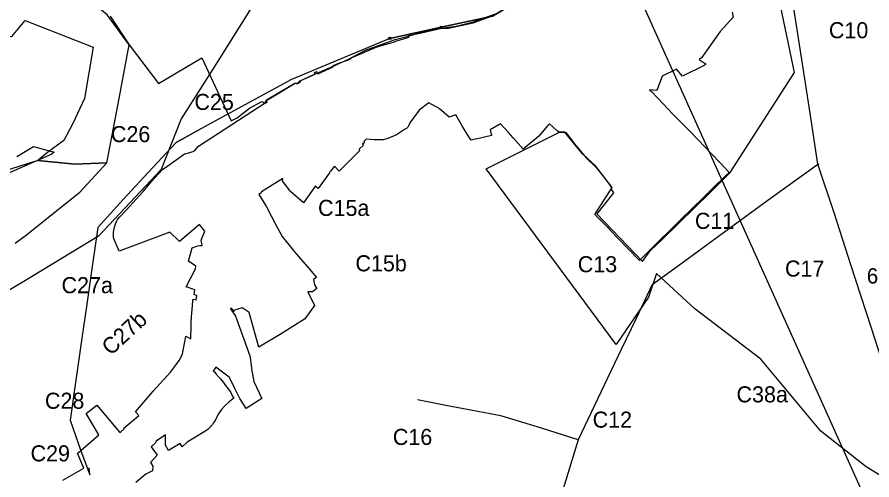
# Model space of a CAD drawing. Extents: x -557103 to -548162, y -1041918 to -1033974.
# Drawn here: x -553807 to -552210, y -1037353 to -1036489 of the extents above; entities that cross this region are included whole.
import ezdxf

# ---------------------------------------------------------------- set-up
doc = ezdxf.new("R2010")
doc.units = 0
for name, color, linetype in [('body3', 7, 'Continuous'), ('Vrstva 14', 7, 'Continuous'), ('Vrstva 15', 7, 'Continuous'), ('Vrstva 16', 7, 'Continuous'), ('Vrstva 37', 7, 'Continuous'), ('Vrstva 49', 7, 'Continuous'), ('Vrstva 9', 7, 'Continuous')]:
    doc.layers.add(name, color=color, linetype=linetype)

msp = doc.modelspace()

# ---------------------------------------------------------------- linework, layer by layer
at = {"layer": 'body3'}
for p, q in [((-552954.6, -1036498.2), (-552914.9, -1036483.5)), ((-552471.1, -1036479.8), (-552469.1, -1036489.2)), ((-552986.9, -1036505.9), (-552954.6, -1036498.2)), ((-552469.1, -1036489.2), (-552493.6, -1036516.3)), ((-553051.5, -1036518.7), (-553014.5, -1036509.9)), ((-553014.5, -1036509.9), (-552986.9, -1036505.9)), ((-552493.6, -1036516.3), (-552528.4, -1036565)), ((-553099.3, -1036534.1), (-553075, -1036526.8)), ((-553075.8, -1036523.8), (-553051.6, -1036518.5)), ((-553075, -1036526.8), (-553075.8, -1036523.8)), ((-553051.6, -1036518.5), (-553051.5, -1036518.7)), ((-553153.9, -1036553.1), (-553136, -1036545.5)), ((-553136, -1036545.5), (-553124.5, -1036541.5)), ((-553124.5, -1036541.5), (-553104.1, -1036535.9)), ((-553104.1, -1036535.9), (-553099.3, -1036534.1)), ((-553183.1, -1036565.1), (-553163.8, -1036557.1)), ((-553163.8, -1036557.1), (-553153.9, -1036553.1)), ((-553217.5, -1036580.4), (-553207.9, -1036576)), ((-553216.7, -1036582), (-553217.5, -1036580.4)), ((-553207.9, -1036576), (-553188, -1036569)), ((-553188, -1036569), (-553183.2, -1036566.4)), ((-553183.2, -1036566.4), (-553183.1, -1036565.1)), ((-552523.4, -1036579.7), (-552564, -1036599.8)), ((-552528.4, -1036565), (-552533, -1036568.5)), ((-552533, -1036568.5), (-552519.9, -1036576.8)), ((-552519.9, -1036576.8), (-552523.4, -1036579.7)), ((-553276.8, -1036607.5), (-553246, -1036593)), ((-553246, -1036593), (-553245.3, -1036595)), ((-553245.3, -1036595), (-553216.7, -1036582)), ((-552575.4, -1036586.2), (-552602, -1036599.8)), ((-552564, -1036599.8), (-552575.4, -1036586.2)), ((-553282.7, -1036613.1), (-553278, -1036610.6)), ((-553278, -1036610.6), (-553277.9, -1036609.3)), ((-553277.9, -1036609.3), (-553277.7, -1036608.1)), ((-553277.7, -1036608.1), (-553276.8, -1036607.5)), ((-552602, -1036599.8), (-552611.9, -1036626.4)), ((-553330, -1036638.1), (-553287.5, -1036612.4)), ((-553287.5, -1036612.4), (-553285.2, -1036613)), ((-553285.2, -1036613), (-553284.2, -1036613.1)), ((-553284.2, -1036613.1), (-553282.7, -1036613.1)), ((-552611.9, -1036626.4), (-552625.8, -1036624.8)), ((-552625.8, -1036624.8), (-552622, -1036628.3)), ((-552622, -1036628.3), (-552610.3, -1036640.7)), ((-553342.1, -1036645), (-553330, -1036638.1)), ((-552610.3, -1036640.7), (-552581.1, -1036670.8)), ((-553418.7, -1036697.9), (-553343.6, -1036649.1)), ((-553343.6, -1036649.1), (-553342.7, -1036649.1)), ((-553342.7, -1036649.1), (-553340.2, -1036647.3)), ((-553340.2, -1036647.3), (-553342.1, -1036645)), ((-553037.8, -1036649.3), (-553056, -1036663)), ((-553018.6, -1036659.9), (-553037.8, -1036649.3)), ((-553000, -1036676), (-553018.6, -1036659.9)), ((-553056, -1036663), (-553073.2, -1036686.7)), ((-552987.3, -1036671.8), (-553000, -1036676)), ((-552974.9, -1036693.8), (-552987.3, -1036671.8)), ((-552581.1, -1036670.8), (-552570.6, -1036681.6)), ((-553073.2, -1036686.7), (-553076.7, -1036694)), ((-552903.9, -1036688.5), (-552923.2, -1036699.6)), ((-552889.2, -1036705), (-552903.9, -1036688.5)), ((-552815.3, -1036691.7), (-552829.6, -1036708.4)), ((-552812.7, -1036688.5), (-552815.3, -1036691.7)), ((-552798.6, -1036700.7), (-552812.7, -1036688.5)), ((-552570.6, -1036681.6), (-552566.5, -1036685.9)), ((-552566.5, -1036685.9), (-552562.3, -1036690.2)), ((-552562.3, -1036690.2), (-552560.2, -1036692.4)), ((-553468.4, -1036730.1), (-553418.7, -1036697.9)), ((-553083.1, -1036699.4), (-553098.4, -1036708.9)), ((-553079.7, -1036697.2), (-553083.1, -1036699.4)), ((-553076.7, -1036694), (-553079.7, -1036697.2)), ((-552962.2, -1036714.7), (-552974.9, -1036693.8)), ((-552923.2, -1036699.6), (-552920.7, -1036710.5)), ((-552880.2, -1036714.7), (-552889.2, -1036705)), ((-552796.5, -1036702.4), (-552798.6, -1036700.7)), ((-552795, -1036703.9), (-552796.5, -1036702.4)), ((-552784.7, -1036703.6), (-552795, -1036703.9)), ((-552750.6, -1036744.6), (-552784.7, -1036703.6)), ((-552560.2, -1036692.4), (-552555.9, -1036696.7)), ((-552555.9, -1036696.7), (-552549.7, -1036703)), ((-552549.7, -1036703), (-552494.8, -1036759.9)), ((-553157.8, -1036723.5), (-553159.8, -1036725.3)), ((-553155.2, -1036717.3), (-553159.6, -1036721.6)), ((-553159.6, -1036721.6), (-553157.8, -1036723.5)), ((-553139.7, -1036718.3), (-553155.2, -1036717.3)), ((-553123, -1036718.1), (-553139.7, -1036718.3)), ((-553114.3, -1036715.8), (-553123, -1036718.1)), ((-553098.4, -1036708.9), (-553114.3, -1036715.8)), ((-552958.7, -1036719.1), (-552962.2, -1036714.7)), ((-552951.6, -1036717.4), (-552958.7, -1036719.1)), ((-552947.2, -1036716.5), (-552951.6, -1036717.4)), ((-552920.7, -1036710.5), (-552947.2, -1036716.5)), ((-552861.7, -1036735.7), (-552880.2, -1036714.7)), ((-552832.4, -1036711.7), (-552861.7, -1036735.7)), ((-552829.6, -1036708.4), (-552832.4, -1036711.7)), ((-553807.4, -1036749.5), (-553776.2, -1036731)), ((-553776.2, -1036731), (-553738.1, -1036741.4)), ((-553478.5, -1036740.4), (-553475.5, -1036738.9)), ((-553475.5, -1036738.9), (-553468.4, -1036730.1)), ((-553167.2, -1036738.8), (-553174.5, -1036746.1)), ((-553160.2, -1036728.3), (-553168.2, -1036736)), ((-553168.2, -1036736), (-553167.2, -1036738.8)), ((-553160.4, -1036724.7), (-553162.1, -1036726.3)), ((-553162.1, -1036726.3), (-553160.2, -1036728.3)), ((-553159.8, -1036725.3), (-553160.4, -1036724.7)), ((-553743.7, -1036745.8), (-553823, -1036780.5)), ((-553738.1, -1036741.4), (-553743.7, -1036745.8)), ((-553525.7, -1036766.7), (-553494.5, -1036744.4)), ((-553494.5, -1036744.4), (-553490.5, -1036743.7)), ((-553490.5, -1036743.7), (-553480.4, -1036740.8)), ((-553480.4, -1036740.8), (-553478.5, -1036740.4)), ((-553174.5, -1036746.1), (-553184.7, -1036756.2)), ((-552726.6, -1036766.9), (-552750.6, -1036744.6)), ((-553535.2, -1036774.1), (-553525.7, -1036766.7)), ((-553214.4, -1036767.5), (-553221.7, -1036777.2)), ((-553205.3, -1036776.9), (-553214.4, -1036767.5)), ((-553184.7, -1036756.2), (-553205.3, -1036776.9)), ((-552695.3, -1036807.5), (-552726.6, -1036766.9)), ((-552494.8, -1036759.9), (-552492.4, -1036762.4)), ((-552492.4, -1036762.4), (-552476.8, -1036779.2)), ((-553556.3, -1036796.4), (-553535.2, -1036774.1)), ((-553223.3, -1036779.8), (-553244.8, -1036809.2)), ((-553223.2, -1036778.9), (-553223.3, -1036779.8)), ((-553221.7, -1036777.2), (-553223.2, -1036778.9)), ((-552483.7, -1036785.9), (-552492.4, -1036794.4)), ((-552476.8, -1036779.2), (-552483.7, -1036785.9)), ((-553571.1, -1036814), (-553556.3, -1036796.4)), ((-553310.7, -1036790.7), (-553350.6, -1036815.2)), ((-553311.2, -1036794.7), (-553310.7, -1036790.7)), ((-553306.1, -1036801.6), (-553311.2, -1036794.7)), ((-553299.7, -1036810.6), (-553306.1, -1036801.6)), ((-552498.9, -1036800.8), (-552505.5, -1036807.1)), ((-552492.4, -1036794.4), (-552498.9, -1036800.8)), ((-553584.5, -1036829.5), (-553571.1, -1036814)), ((-553351.3, -1036817.1), (-553355.3, -1036820.3)), ((-553350.6, -1036815.2), (-553351.3, -1036817.1)), ((-553297.4, -1036813.5), (-553299.7, -1036810.6)), ((-553296.3, -1036814.9), (-553297.4, -1036813.5)), ((-553272.3, -1036836), (-553296.3, -1036814.9)), ((-553249.5, -1036804.6), (-553272.3, -1036836)), ((-553247.7, -1036806.5), (-553249.5, -1036804.6)), ((-553244.8, -1036809.2), (-553247.7, -1036806.5)), ((-552727.9, -1036857.6), (-552695.3, -1036807.5)), ((-552516.2, -1036817.7), (-552520.5, -1036822)), ((-552514.1, -1036815.5), (-552516.2, -1036817.7)), ((-552512, -1036813.5), (-552514.1, -1036815.5)), ((-552505.5, -1036807.1), (-552512, -1036813.5)), ((-553603, -1036849.4), (-553584.5, -1036829.5)), ((-553355.3, -1036820.3), (-553342.1, -1036842.5)), ((-552529.1, -1036830.4), (-552542.1, -1036843)), ((-552520.5, -1036822), (-552529.1, -1036830.4)), ((-553615, -1036862.4), (-553603, -1036849.4)), ((-553342.1, -1036842.5), (-553332, -1036861.5)), ((-552546.4, -1036847.2), (-552566, -1036866)), ((-552544.3, -1036845.1), (-552546.4, -1036847.2)), ((-552542.1, -1036843), (-552544.3, -1036845.1)), ((-553620.7, -1036869.5), (-553619.4, -1036867.1)), ((-553619.4, -1036867.1), (-553615, -1036862.4)), ((-553332, -1036861.5), (-553323.7, -1036877.1)), ((-552702.8, -1036883), (-552727.9, -1036857.6)), ((-552566, -1036866), (-552627.4, -1036927)), ((-553627.1, -1036890.8), (-553625.4, -1036881.2)), ((-553625.4, -1036881.2), (-553623.2, -1036875.5)), ((-553623.2, -1036875.5), (-553620.7, -1036869.5)), ((-553466.6, -1036876.3), (-553504, -1036908.4)), ((-553456.5, -1036888.8), (-553466.6, -1036876.3)), ((-553323.7, -1036877.1), (-553316.2, -1036891)), ((-552687.1, -1036899.6), (-552702.8, -1036883)), ((-553626.9, -1036901.6), (-553627.1, -1036890.8)), ((-553521.9, -1036890.9), (-553616.2, -1036926.4)), ((-553504, -1036908.4), (-553521.9, -1036890.9)), ((-553463.1, -1036905.8), (-553456.5, -1036888.8)), ((-553316.2, -1036891), (-553311.9, -1036899)), ((-553311.9, -1036899), (-553291.2, -1036924.5)), ((-552644.4, -1036943.8), (-552687.1, -1036899.6)), ((-553616.2, -1036926.4), (-553626.9, -1036901.6)), ((-553469.7, -1036916.2), (-553465.6, -1036915.7)), ((-553465.6, -1036915.7), (-553461.3, -1036915.5)), ((-553461.3, -1036915.5), (-553463.1, -1036905.8)), ((-553487, -1036945.2), (-553480.3, -1036920.1)), ((-553480.3, -1036920.1), (-553469.7, -1036916.2)), ((-553291.2, -1036924.5), (-553281.8, -1036935.6)), ((-552627.4, -1036927), (-552644.4, -1036943.8)), ((-553472.9, -1036954.3), (-553487, -1036945.2)), ((-553281.8, -1036935.6), (-553264.2, -1036956.5)), ((-553491, -1036992.8), (-553474, -1036959.3)), ((-553474, -1036959.3), (-553472.9, -1036954.3)), ((-553264.2, -1036956.5), (-553247.8, -1036975.2)), ((-553250.7, -1036977.4), (-553253.2, -1036979.3)), ((-553253.2, -1036979.3), (-553251.8, -1036989.1)), ((-553247.8, -1036975.2), (-553250.7, -1036977.4)), ((-553475.1, -1036998.7), (-553491, -1036992.8)), ((-553251.8, -1036989.1), (-553246.9, -1036995.9)), ((-553476.6, -1037008.1), (-553475.1, -1036998.7)), ((-553471.6, -1037008.9), (-553476.6, -1037008.1)), ((-553472.6, -1037017), (-553471.6, -1037008.9)), ((-553255, -1037002), (-553264.1, -1037002.5)), ((-553264.1, -1037002.5), (-553251.2, -1037027.9)), ((-553246.9, -1036995.9), (-553255, -1037002)), ((-553479.5, -1037028.3), (-553478.9, -1037017.8)), ((-553478.9, -1037017.8), (-553478, -1037015.8)), ((-553478, -1037015.8), (-553472.6, -1037017)), ((-553481.1, -1037049.2), (-553479.8, -1037035)), ((-553479.8, -1037035), (-553479.5, -1037028.3)), ((-553406.7, -1037032.5), (-553408.5, -1037034.1)), ((-553408.5, -1037034.1), (-553399.4, -1037047.4)), ((-553402, -1037039.4), (-553406.7, -1037032.5)), ((-553386.6, -1037032.2), (-553402.6, -1037037.1)), ((-553402.6, -1037037.1), (-553402, -1037039.4)), ((-553373.3, -1037041.1), (-553386.6, -1037032.2)), ((-553355.4, -1037105.8), (-553373.3, -1037041.1)), ((-553251.2, -1037027.9), (-553267.5, -1037050.4)), ((-553482, -1037064.5), (-553481.7, -1037059.6)), ((-553481.7, -1037059.6), (-553481.1, -1037049.2)), ((-553399.4, -1037047.4), (-553398.9, -1037047.8)), ((-553398.9, -1037047.8), (-553397, -1037052.5)), ((-553397, -1037052.5), (-553372.3, -1037121.5)), ((-553270.1, -1037053), (-553313.9, -1037080.8)), ((-553267.5, -1037050.4), (-553270.1, -1037053)), ((-553482.4, -1037090.2), (-553482, -1037064.5)), ((-553498, -1037118), (-553492.7, -1037089.5)), ((-553492.7, -1037089.5), (-553492.1, -1037085.3)), ((-553492.1, -1037085.3), (-553482.4, -1037090.2)), ((-553313.9, -1037080.8), (-553355.4, -1037105.8)), ((-553504.6, -1037130.4), (-553499.9, -1037122.6)), ((-553499.9, -1037122.6), (-553498, -1037118)), ((-553372.3, -1037121.5), (-553371.7, -1037125.6)), ((-553520.8, -1037152), (-553509.6, -1037137.4)), ((-553509.6, -1037137.4), (-553504.6, -1037130.4)), ((-553371.7, -1037125.6), (-553369.9, -1037139)), ((-553369.9, -1037139), (-553368.7, -1037150.1)), ((-553553.1, -1037187.5), (-553520.8, -1037152)), ((-553440.4, -1037148.9), (-553440.8, -1037149.6)), ((-553440.8, -1037149.6), (-553437.8, -1037152.5)), ((-553435.9, -1037143.1), (-553440.4, -1037148.9)), ((-553437.8, -1037152.5), (-553435.4, -1037156.2)), ((-553428.6, -1037148.4), (-553435.9, -1037143.1)), ((-553411, -1037161.9), (-553428.6, -1037148.4)), ((-553368.7, -1037150.1), (-553367.6, -1037156)), ((-553435.4, -1037156.2), (-553429.8, -1037162.2)), ((-553429.8, -1037162.2), (-553427.4, -1037164.9)), ((-553427.4, -1037164.9), (-553422.4, -1037170.9)), ((-553422.4, -1037170.9), (-553420.5, -1037173.6)), ((-553401.7, -1037179.4), (-553411, -1037161.9)), ((-553367.6, -1037156), (-553364.7, -1037169.4)), ((-553364.7, -1037169.4), (-553349.9, -1037201.4)), ((-553420.5, -1037173.6), (-553417.6, -1037177.2)), ((-553417.6, -1037177.2), (-553412.7, -1037183.5)), ((-553412.7, -1037183.5), (-553408, -1037190)), ((-553400.1, -1037182.5), (-553401.7, -1037179.4)), ((-553397.8, -1037187.6), (-553400.1, -1037182.5)), ((-553586, -1037226.3), (-553556.3, -1037191.4)), ((-553556.3, -1037191.4), (-553553.1, -1037187.5)), ((-553402.5, -1037200.6), (-553411.6, -1037208.3)), ((-553408, -1037190), (-553404.5, -1037196.8)), ((-553404.5, -1037196.8), (-553402.5, -1037200.6)), ((-553397.6, -1037187.6), (-553397.8, -1037187.6)), ((-553391.1, -1037201.5), (-553397.6, -1037187.6)), ((-553378.9, -1037220.2), (-553391.1, -1037201.5)), ((-553349.9, -1037201.4), (-553378.9, -1037220.2)), ((-553678.1, -1037229.2), (-553658.4, -1037214.2)), ((-553658.4, -1037214.2), (-553615.4, -1037265)), ((-553420.2, -1037216.1), (-553425.5, -1037221.7)), ((-553417.3, -1037213.5), (-553420.2, -1037216.1)), ((-553411.6, -1037208.3), (-553417.3, -1037213.5)), ((-553654.7, -1037269.3), (-553678.1, -1037229.2)), ((-553608, -1037257.1), (-553579.7, -1037233.3)), ((-553579.7, -1037233.3), (-553586, -1037226.3)), ((-553431.6, -1037230.6), (-553435.2, -1037238.9)), ((-553425.5, -1037221.7), (-553431.6, -1037230.6)), ((-553442.1, -1037249.8), (-553448.5, -1037257.1)), ((-553440.6, -1037247.7), (-553442.1, -1037249.8)), ((-553438.8, -1037245), (-553440.6, -1037247.7)), ((-553435.9, -1037239.8), (-553438.8, -1037245)), ((-553435.2, -1037238.9), (-553435.9, -1037239.8)), ((-553615.4, -1037265), (-553613.5, -1037263.6)), ((-553613.5, -1037263.6), (-553607.1, -1037258.4)), ((-553607.1, -1037258.4), (-553608, -1037257.1)), ((-553456.6, -1037262.8), (-553489.4, -1037283.1)), ((-553451.1, -1037259.2), (-553456.6, -1037262.8)), ((-553448.5, -1037257.1), (-553451.1, -1037259.2)), ((-553688.2, -1037298.5), (-553669.7, -1037282.5)), ((-553669.7, -1037282.5), (-553654.7, -1037269.3)), ((-553547.3, -1037280.9), (-553549.2, -1037285)), ((-553529.6, -1037269.6), (-553547.3, -1037280.9)), ((-553529.9, -1037288.8), (-553529.6, -1037269.6)), ((-553489.4, -1037283.1), (-553498.7, -1037291.4)), ((-553694.2, -1037303.8), (-553688.2, -1037298.5)), ((-553549.2, -1037285), (-553556.4, -1037291.6)), ((-553556.4, -1037291.6), (-553545.4, -1037307.2)), ((-553524.2, -1037298.8), (-553529.9, -1037288.8)), ((-553502.4, -1037285.6), (-553524.2, -1037298.8)), ((-553498.7, -1037291.4), (-553502.4, -1037285.6)), ((-553684.7, -1037325.9), (-553694.2, -1037303.8)), ((-553545.4, -1037307.2), (-553557.9, -1037320.7)), ((-553682.3, -1037331.5), (-553684.7, -1037325.9)), ((-553557.9, -1037320.7), (-553556.8, -1037322.6)), ((-553556.8, -1037322.6), (-553553.7, -1037327.8)), ((-553553.7, -1037327.8), (-553554.2, -1037336.8)), ((-553721.7, -1037354.2), (-553682.3, -1037331.5)), ((-553566.5, -1037342.5), (-553585.3, -1037358.6)), ((-553554.2, -1037336.8), (-553566.5, -1037342.5))]:
    msp.add_line(p, q, dxfattribs=at)
at = {"layer": 'Vrstva 14'}
msp.add_lwpolyline([(-551661.8, -1038633.9), (-553519.6, -1034507.2), (-553504.9, -1034676.5)], dxfattribs=at)
at = {"layer": 'Vrstva 15'}
for p, q in [((-553062.2, -1036527.1), (-553062.2, -1036527.1)), ((-553671.5, -1037343.8), (-553672.5, -1037330.8))]:
    msp.add_line(p, q, dxfattribs=at)
for points in [[(-552535.4, -1036171.2), (-552583.7, -1036224.7), (-552638.1, -1036285), (-552707.1, -1036361.3), (-552775.2, -1036401.6), (-552849.1, -1036445.3), (-552919, -1036487.2), (-553014.6, -1036507.9)], [(-552310.8, -1036764.1), (-552323.4, -1036681.2), (-552336.9, -1036596.1), (-552355.9, -1036472.4), (-552376.6, -1036410.5), (-552393.7, -1036360.2), (-552422.4, -1036321.6)], [(-553014.6, -1036507.9), (-553110.6, -1036528.9), (-553200.2, -1036566.4), (-553294.3, -1036605.6)], [(-553294.3, -1036605.6), (-553373.6, -1036648.7), (-553451.2, -1036691.2), (-553510.8, -1036723.7), (-553562.2, -1036779.2), (-553608.7, -1036829.8), (-553656.5, -1036882), (-553666.4, -1036950.7), (-553677.1, -1037025), (-553687, -1037093.3), (-553698.8, -1037175.7), (-553707.9, -1037241.7), (-553688.5, -1037297.2), (-553671.5, -1037343.8)], [(-552620.8, -1036988.5), (-552571.2, -1036952.8), (-552482.9, -1036888.1), (-552397.7, -1036826.3), (-552309.1, -1036762.8), (-552309.1, -1036762.8)], [(-552068.1, -1037512.6), (-552118.7, -1037355.6), (-552166.5, -1037207.2), (-552210.9, -1037069.8), (-552249.3, -1036951.7), (-552280.1, -1036856.3), (-552310.8, -1036764.1)], [(-552620.8, -1036988.5), (-552650.4, -1037051.8), (-552678.4, -1037110.2), (-552716.5, -1037189.6), (-552758.6, -1037278.6)], [(-552759.1, -1037278.6), (-552827.5, -1037257), (-552903.3, -1037234.1), (-552956.5, -1037224), (-553006.1, -1037214.6), (-553059, -1037204.2)], [(-552758.6, -1037278.6), (-552793.9, -1037392.6), (-552821.1, -1037475.8), (-552845.2, -1037552.1), (-552871.1, -1037634.9), (-552897.9, -1037720.2), (-552946.1, -1037812.1)]]:
    msp.add_lwpolyline(points, dxfattribs=at)
at = {"layer": 'Vrstva 16'}
msp.add_lwpolyline([(-553009.6, -1035496.7), (-553002.1, -1035544), (-553049.5, -1035622.1), (-553086.8, -1035719.3), (-553126.7, -1035856.4), (-553136.7, -1035986), (-553156.6, -1036068.2), (-553271.2, -1036329.9), (-553326, -1036402.2), (-553438.1, -1036581.7), (-553500.4, -1036678.9), (-553537.8, -1036773.6), (-553654.9, -1036898.3), (-553794.4, -1036983), (-553946.4, -1037072.7), (-554030.9, -1037138.8), (-554140.5, -1037236), (-554172.9, -1037275.9), (-554409.6, -1037435.4)], dxfattribs=at)
at = {"layer": 'Vrstva 49'}
msp.add_line((-553110.6, -1036528.9), (-553014.6, -1036507.9), dxfattribs=at)
for points in [[(-553014.6, -1036507.9), (-552919.1, -1036487.2), (-552848.6, -1036445.3), (-552775.2, -1036401.6), (-552707.1, -1036361.3), (-552672.7, -1036395.9), (-552630.1, -1036437.8)], [(-553110.6, -1036528.9), (-553200.2, -1036566.4), (-553294.3, -1036605.6), (-553373.6, -1036648.7), (-553451.2, -1036691.2), (-553511.3, -1036723.7)]]:
    msp.add_lwpolyline(points, dxfattribs=at)
for centre, radius in [((-553014.6, -1036507.9), 1.82), ((-553014.6, -1036507.9), 1.1), ((-553110.6, -1036528.9), 2.44), ((-553110.6, -1036528.9), 1.08)]:
    msp.add_circle(centre, radius, dxfattribs=at)
at = {"layer": 'Vrstva 9'}
for points in [[(-553787.5, -1036333.8), (-553960.5, -1036330.1), (-553891.5, -1036520.6), (-553817, -1036525.2), (-553792.1, -1036495.8), (-553665.2, -1036545.5), (-553681.2, -1036641.3), (-553702.9, -1036687.9), (-553719.7, -1036719.8), (-553750.4, -1036742), (-553768.5, -1036756.7)], [(-553768.5, -1036756.7), (-553699.2, -1036764), (-553639.4, -1036761.2), (-553620.1, -1036660.9), (-553598, -1036541.2), (-553638.1, -1036485.4), (-553664, -1036464.5), (-553771.5, -1036351), (-553787.5, -1036333.8)], [(-552181.9, -1037352.7), (-552220.5, -1037328.8), (-552305.2, -1037262.5), (-552417.4, -1037128.1), (-552540.7, -1037034.2), (-552612.5, -1036968), (-552627.2, -1037012.1), (-552688, -1037100.5), (-552930.9, -1036772.8), (-552794.7, -1036704.7), (-552792.1, -1036703.8), (-552782.2, -1036704.4), (-552765.7, -1036725.6), (-552743.8, -1036752), (-552724.7, -1036770.5), (-552706.6, -1036793.9), (-552696.6, -1036807.5), (-552698, -1036810), (-552692.8, -1036817.4), (-552723.9, -1036856.6), (-552638.5, -1036945.5), (-552624.5, -1036925.9), (-552600.3, -1036902.5), (-552600.3, -1036902.5), (-552513.1, -1036817.2), (-552474.8, -1036779.6), (-552354.8, -1036592.7), (-552400, -1036374.7)], [(-553633, -1036487.5), (-553598, -1036541.2), (-553542.8, -1036613.2), (-553461.8, -1036565.3), (-553407.5, -1036683.2)], [(-553407.5, -1036683.2), (-553396.1, -1036677.6), (-553372.9, -1036659), (-553350.2, -1036646.8), (-553344.2, -1036650.1), (-553341.3, -1036643.5), (-553288.1, -1036612.5), (-553282.1, -1036612.4), (-553278.1, -1036608.4), (-553250.2, -1036595.5), (-553251.3, -1036592.8), (-553247.2, -1036591), (-553247.2, -1036591), (-553246.4, -1036593.6), (-553217.8, -1036581.5), (-553188.2, -1036567.5), (-553156.5, -1036551), (-553100.7, -1036531.2), (-553076.4, -1036524.7), (-553050.9, -1036517.1), (-553050.9, -1036517.1), (-553014.5, -1036509.9), (-553001.2, -1036509.9), (-552955, -1036499.8), (-552916.1, -1036485.5)], [(-553810.5, -1036911.2), (-553792.1, -1036897.4), (-553690, -1036816.4), (-553639.4, -1036761.2), (-553699.2, -1036764), (-553768.5, -1036756.7), (-553829.4, -1036776.6)]]:
    msp.add_lwpolyline(points, dxfattribs=at)

# ---------------------------------------------------------------- texts
at = {"layer": 'Vrstva 37'}
for s, p in [('C10', (-552290.4, -1036528.7)), ('C25', (-553475.8, -1036662.6)), ('C26', (-553631.9, -1036722.7)), ('C15a', (-553244.9, -1036860.5)), ('C11', (-552540.7, -1036884.7)), ('C15b', (-553175, -1036964)), ('C13', (-552759.6, -1036965.7)), ('C17', (-552372.4, -1036973.8)), ('C27a', (-553724.1, -1037004.8)), ('C38a', (-552463, -1037208.7)), ('C28', (-553755.1, -1037220.6)), ('C12', (-552731.8, -1037255.9)), ('C16', (-553105.1, -1037288.2)), ('C29', (-553782, -1037318.9))]:
    msp.add_text(s, height=30, dxfattribs=at).set_placement(p)
msp.add_text('C27b', height=30, rotation=42.7094, dxfattribs=at).set_placement((-553632.1, -1037122.6))
at = {"layer": 'Vrstva 9'}
msp.add_text('61,70', height=28.5, dxfattribs=at).set_placement((-552219.5, -1036986.7))

doc.saveas('drawing.dxf')
